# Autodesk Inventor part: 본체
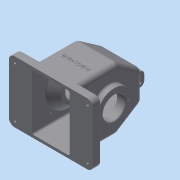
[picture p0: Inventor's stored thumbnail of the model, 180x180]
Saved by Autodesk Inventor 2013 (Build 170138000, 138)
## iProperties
Created: 2016-12
Part Number: 본체
Material: 일반
Document SubType Name: Modeling
Designer: Administrator
Density: 1 g/cm^3
Author: Administrator
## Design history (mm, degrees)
sketch "스케치4"
  geometry: L1 (65, -55)-(-65, -55); L2 (-75, -45)-(-75, 45); L3 (-65, 55)-(65, 55); L4 (75, 45)-(75, -45); L5 (75, -55)-(-75, 55); L6 (-75, -55)-(75, 55); A1 r 10 centre (65, -45) between (65, -55) and (75, -45); A2 r 10 centre (65, 45) between (75, 45) and (65, 55); A3 r 10 centre (-65, 45) between (-65, 55) and (-75, 45); A4 r 10 centre (-65, -45) between (-75, -45) and (-65, -55); 1 further point
  constraints: 12 end point, 8 point on circle, 8 point on line, 8 tangent, 4 centre point, 3 equal radius, 2 midpoint, 2 parallel, 1 horizontal, 1 perpendicular
  dimensions: "d4" = 150 distance of L5.start L6.start; "d6" = 110 distance of L6.start L5.end; "d7" = 10 radius of A1
sketch "스케치6"
  geometry: L1 (15, -55)-(0, -55) reference; L2 (0, -55)-(0, 55) reference; L3 (0, 55)-(15, 55) reference; L4 (15, 55)-(15, -55) reference; L5 (15, 55)-(81.402, 55); L6 (81.402, 55)-(125, 24.472); L7 (125, 24.472)-(125, -26.579); L8 (125, -26.579)-(80, -55); L9 (80, -55)-(15, -55); 1 further point
  constraints: 10 end point, 2 perpendicular, 1 equal length, 1 parallel
  dimensions: "d17" = 80 distance of L1.end L8.end; "d18" = 35 deg angle of L5 L6; "d19" = 125 distance between parallel lines of L2 L7
extrude "돌출2" join sketch "스케치6" stored distance "d20" = 77; taper "d21" = 0 deg
feature "쉘1" dims "d38" = 5
extrude "돌출5" join sketch "스케치4" distance "d39" = 15; taper "d40" = 0 deg
sketch "스케치13"
  geometry: L1 (-33.5, 15)-(33.5, 15) reference; L2 (33.5, 15)-(33.5, 120) reference; L3 (33.5, 120)-(-33.5, 120) reference; L4 (-33.5, 120)-(-33.5, 15) reference; L5 (75, 0)-(-75, 0) reference; L6 (-75, 0)-(-75, 15) reference; L7 (-75, 15)-(-38.5, 15) reference; L8 (-38.5, 15)-(-38.5, 125) reference; L9 (-38.5, 125)-(38.5, 125) reference; L10 (38.5, 125)-(38.5, 15) reference; L11 (38.5, 15)-(75, 15) reference; L12 (75, 15)-(75, 0) reference; L13 (-33.5, 15)-(-33.5, 0); L14 (33.5, 15)-(33.5, 0); 1 further point
  constraints: 4 end point, 2 perpendicular, 2 point on line
extrude "돌출6" cut sketch "스케치13" stored distance "d41" = 100; taper "d42" = 0 deg
sketch "스케치14"
  geometry: L1 (-65, 55)-(-38.5, 55) reference; L2 (-38.5, 55)-(38.5, 55) reference; L3 (38.5, 55)-(38.5, -55) reference; L4 (65, -55)-(38.5, -55) reference; L5 (75, 45)-(75, -45) reference; L6 (38.5, 55)-(65, 55) reference; L7 (-75, -45)-(-75, 45) reference; L8 (-38.5, -55)-(-65, -55) reference; L9 (38.5, -55)-(-38.5, -55) reference; L10 (-38.5, -55)-(-38.5, 55) reference; L11 (-38.5, 55)-(-38.5, -55) reference; L12 (-38.5, 55)-(-65, 55) reference; L13 (-75, 45)-(-75, -45) reference; L14 (-65, -55)-(-38.5, -55) reference; L15 (38.5, -55)-(38.5, 55) reference; L16 (38.5, -55)-(65, -55) reference; L17 (75, -45)-(75, 45) reference; L18 (65, 55)-(38.5, 55) reference; L19 (-33.5, 50)-(-33.5, -50) reference; L20 (-33.5, -50)-(33.5, -50) reference; L21 (33.5, -50)-(33.5, 50) reference; L22 (33.5, 50)-(-33.5, 50) reference; A1 r 10 centre (65, -45) between (65, -55) and (75, -45) reference; A2 r 10 centre (65, 45) between (75, 45) and (65, 55) reference; A3 r 10 centre (-65, 45) between (-65, 55) and (-75, 45) reference; A4 r 10 centre (-65, -45) between (-75, -45) and (-65, -55) reference; A5 r 10 centre (-65, 45) between (-65, 55) and (-75, 45) reference; A6 r 10 centre (-65, -45) between (-75, -45) and (-65, -55) reference; A7 r 10 centre (65, -45) between (65, -55) and (75, -45) reference; A8 r 10 centre (65, 45) between (75, 45) and (65, 55) reference; 5 further points
  constraints: 4 coincident
hole "구멍2" sketch "스케치14" at (-65, 45), (65, 45), (65, -45), (-65, -45) diameter "d43" = 5; stored, may be unused: countersink angle "d47" = 90 deg, drill point angle "d49" = 118 deg; dims "d44" = 6, "d45" = 12, "d46" = 5, "d48" = 8
sketch "스케치15"
  geometry: L1 (-73.148, 65)-(76.59, 65); L2 (45, 0)-(-45, 0) reference; L3 (-55, 80)-(-55, 15) reference; L4 (-55, 15)-(55, 15) reference; L5 (55, 15)-(55, 81.402) reference; L6 (55, 81.402)-(24.472, 125) reference; L7 (24.472, 125)-(-26.579, 125) reference; L8 (-26.579, 125)-(-55, 80) reference; L9 (-1.053, 125)-(-1.053, -16.719); C1 r 37.5 at (-1.053, 65); C2 r 29 at (-1.053, 65); C3 r 20 at (-1.053, 65); 1 further point
  constraints: 4 end point, 3 centre point, 2 coincident, 2 point on line, 1 horizontal, 1 midpoint, 1 perpendicular
  dimensions: "d50" = 65 distance between parallel lines of L2 L1; "d51" = 75 diameter of C1; "d52" = 58 diameter of C2; "d53" = 40 diameter of C3
  node "투영된 루프6"
extrude "돌출7" join sketch "스케치15" distance "d58" = 5; taper "d59" = 0 deg
sketch "스케치19"
  geometry: L1 (-33.5, 0)-(-75, 0) reference; L2 (-75, 0)-(-75, 15) reference; L3 (-75, 15)-(-38.5, 15) reference; L4 (-38.5, 15)-(-38.5, 27.515) reference; L5 (-38.5, 27.515)-(-43.5, 27.515) reference; L6 (-43.5, 27.515)-(-43.5, 102.485) reference; L7 (-43.5, 102.485)-(-38.5, 102.485) reference; L8 (-38.5, 102.485)-(-38.5, 125) reference; L9 (-38.5, 125)-(38.5, 125) reference; L10 (38.5, 125)-(38.5, 15) reference; L11 (38.5, 15)-(75, 15) reference; L12 (75, 15)-(75, 0) reference; L13 (75, 0)-(33.5, 0) reference; L14 (33.5, 0)-(33.5, 120) reference; L15 (33.5, 120)-(-33.5, 120) reference; L16 (-33.5, 120)-(-33.5, 0) reference; L17 (-56.75, 65)-(60.02, 65); L18 (33.5, 0)-(-33.5, 0) reference; L19 (-33.5, 106)-(-19.5, 92); L20 (-19.5, 92)-(-19.5, 65); L21 (-33.5, 106)-(-33.5, 65); 1 further point
  constraints: 8 end point, 4 point on line, 2 perpendicular
  dimensions: "d61" = 65 distance between parallel lines of L18 L17; "d62" = 45 deg angle of L20 L19; "d63" = 54 diameter of L19.end L17; "d64" = 24 distance between parallel lines of L20 L6
revolve "회전1" sketch "스케치19" stored, may be unused: angle "d65" = 90 deg
sketch "스케치20"
  geometry: L1 (-77.082, 65)-(75.36, 65); L2 (55, 15)-(55, 80) reference; L3 (55, 80)-(26.579, 125) reference; L4 (26.579, 125)-(-24.472, 125) reference; L5 (-24.472, 125)-(-55, 81.402) reference; L6 (-55, 81.402)-(-55, 15) reference; L7 (-55, 15)-(55, 15) reference; L8 (45, 0)-(-45, 0) reference; L9 (1.053, 125)-(1.053, -17.949); C1 r 31 at (1.053, 65); C2 r 26 at (1.053, 65); 1 further point
  constraints: 4 end point, 2 centre point, 2 point on line, 1 coincident, 1 horizontal, 1 midpoint, 1 perpendicular
  dimensions: "d66" = 65 distance between parallel lines of L8 L1; "d67" = 62 diameter of C1; "d68" = 52 diameter of C2
extrude "돌출8" join sketch "스케치20" distance "d69" = 10; taper "d70" = 0 deg
extrude "돌출9" cut sketch "스케치15" stored distance "d71" = 10; taper "d72" = 0 deg
sketch "스케치21"
  geometry: 1 further point
sketch "스케치22" dims "d73" = 58
  geometry: C1 r 37.5 at (0, 0) reference; 3 further points
  constraints: 2 vertical alignment, 1 coincident, 2 other
hole "구멍3" sketch "스케치22" at (0, 29) diameter "d75" = 2.459; stored, may be unused: countersink angle "d79" = 90 deg, drill point angle "d81" = 118 deg; dims "d76" = 6, "d77" = 12, "d78" = 5, "d80" = 8
sketch "스케치23" dims "d85" = 52
  geometry: C1 r 31 at (0, 0) reference; 3 further points
  constraints: 2 vertical alignment, 1 coincident, 2 other
hole "구멍4" sketch "스케치23" at (0, 26) diameter "d87" = 2.459; stored, may be unused: countersink angle "d91" = 90 deg, drill point angle "d93" = 118 deg; dims "d88" = 6, "d89" = 12, "d90" = 5, "d92" = 8
node "작업 평면2"
sketch "스케치24"
  geometry: L1 (38.5, 24.472)-(-38.5, 24.472) reference; L2 (-38.5, -26.579)-(-38.5, 24.472) reference; L3 (38.5, -26.579)-(-38.5, -26.579) reference; L4 (38.5, 24.472)-(38.5, -26.579) reference; L5 (24.333, -13.553)-(16.333, -13.553); L6 (16.333, -13.553)-(16.333, 11.447); L7 (16.333, 11.447)-(24.333, 11.447); L8 (24.333, 11.447)-(24.333, -13.553); L9 (-19.667, -13.553)-(-27.667, -13.553); L10 (-27.667, -13.553)-(-27.667, 11.447); L11 (-27.667, 11.447)-(-19.667, 11.447); L12 (-19.667, 11.447)-(-19.667, -13.553); L13 (-38.5, -26.579)-(-38.5, 24.472) reference; L14 (38.5, -1.053)-(-56.15, -1.053); 7 further points
  constraints: 18 end point, 7 midpoint, 4 horizontal alignment, 4 parallel, 3 perpendicular, 2 horizontal, 1 collinear
  dimensions: "d98" = 36 distance between parallel lines of L12 L6; "d100" = 52 distance between parallel lines of L10 L8; "d101" = 25 distance of L5.end L6.end; "d102" = 25 distance of L11.end L9.start
extrude "돌출10" join sketch "스케치24" stored distance "d103" = 10; taper "d104" = 0 deg
sketch "스케치25"
  geometry: L1 (25, -15)-(0, -15) reference; L2 (25, 0)-(25, -15) reference; L3 (25, 0)-(0, 0) reference; L4 (0, 0)-(0, -15) reference; L5 (5, -5)-(20, -5); L6 (20, -5)-(20, -15); L7 (20, -15)-(5, -15); L8 (5, -15)-(5, -5); 3 further points
  constraints: 8 end point, 2 midpoint, 2 parallel, 1 horizontal, 1 perpendicular, 1 point on line, 1 vertical alignment
  dimensions: "d106" = 5 distance between parallel lines of L5 L3; "d107" = 15 distance of L5.start L5.end
extrude "돌출11" cut sketch "스케치25" stored distance "d108" = 10; taper "d109" = 0 deg
sketch "스케치26" dims "d21" = 0
  geometry: L1 (77, 0)-(77, -66.402) reference; L2 (0, 0)-(77, 0) reference; L3 (0, -66.402)-(0, 0) reference; L4 (-26.5, -66.402)-(0, -66.402) reference; L5 (-26.5, -81.402)-(-26.5, -66.402) reference; L6 (103.5, -81.402)-(-26.5, -81.402) reference; L7 (103.5, -81.402)-(103.5, -66.402) reference; L8 (77, -66.402)-(103.5, -66.402) reference; 2 further points
  constraints: 1 other
  dimensions: "d110" = 38.5 distance from line of L3 point (38.5, -36.402); "d111" = 45 distance from line of L6 point (38.5, -36.402)
feature "엠보싱1" sketch "스케치26" dims "d21" = 0, "d112" = 0.5, "d113" = 0
fillet "모깎기1" dims "d114" = 10, "d115" = 8
fillet "모깎기2" dims "d116" = 8
fillet "모깎기3" dims "d117" = 1
fillet "모깎기4" dims "d118" = 8
chamfer "모따기1" distance "d119" = 1; stored, may be unused: second distance "d120" = 2, angle "d121" = 45 deg
fillet "모깎기5" dims "d122" = 3
fillet "모깎기6" dims "d123" = 3
sketch "스케치27"
  geometry: 1 further point
fillet "모깎기7" dims "d124" = 1
fillet "모깎기8" dims "d125" = 1
fillet "모깎기9" dims "d126" = 1
node "솔리드1"
pattern_circular "원형 패턴1" dims angle "d83" = 360 deg
pattern_circular "원형 패턴2" dims angle "d95" = 360 deg
node "투영된 루프4"
node "투영된 루프5"
node "투영된 루프7"
node "투영된 루프8"
node "투영된 루프9"
node "투영된 루프10"
node "절단 모서리 투영1"
node "절단 모서리 투영3"
node "절단 모서리 투영4"
node "절단 모서리 투영6"
